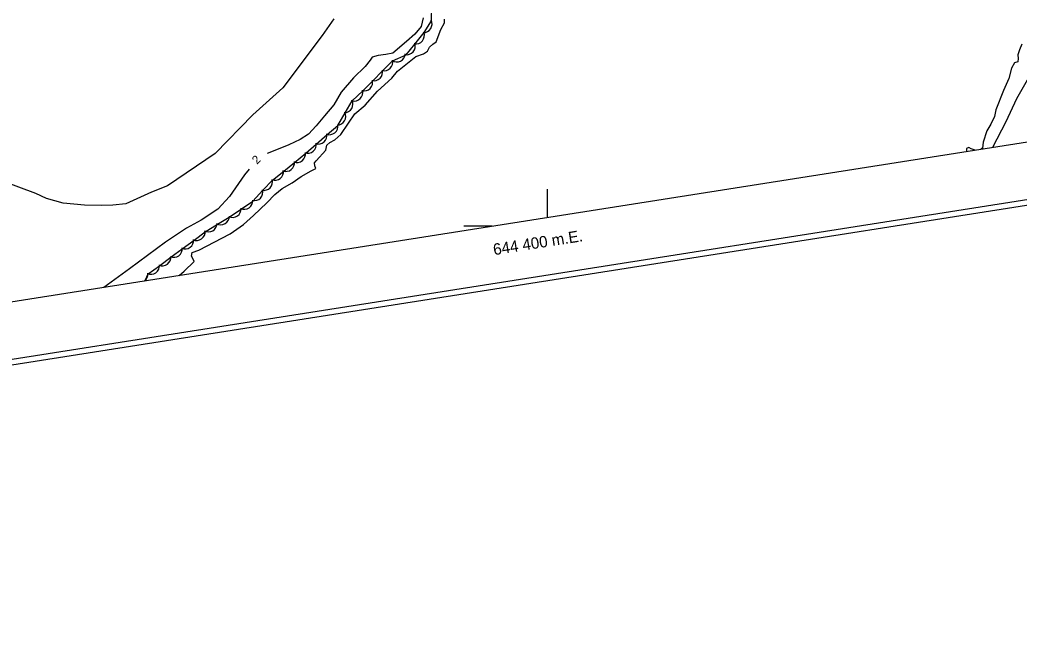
# Model space of a CAD drawing. Extents: x 643342 to 646936, y 5873857 to 5876103.
# Drawn here: x 644214.5 to 644566.3, y 5873857 to 5874072.5 of the extents above; entities that cross this region are included whole.
import ezdxf

# ---------------------------------------------------------------- set-up
doc = ezdxf.new("R2010")
doc.units = 0
for name, color, linetype in [('Niveau 2', 7, 'Continuous'), ('Niveau 22', 7, 'Continuous'), ('Niveau 4', 7, 'Continuous'), ('Niveau 44', 7, 'Continuous'), ('Niveau 60', 7, 'Continuous'), ('Niveau 61', 7, 'Continuous')]:
    doc.layers.add(name, color=color, linetype=linetype)

msp = doc.modelspace()

# ---------------------------------------------------------------- linework, layer by layer
at = {"layer": 'Niveau 2'}
for points in [[(644324.94, 5874072.94), (644320.84, 5874067.04), (644306.96, 5874048.61), (644296.44, 5874039.2), (644283.1, 5874025.54), (644266.37, 5874014.18), (644260.79, 5874011.93), (644251.7, 5874007.83), (644247.13, 5874007.43), (644243.24, 5874007.32), (644237.22, 5874007.38), (644229.71, 5874008.14), (644223.79, 5874009.74), (644220.09, 5874011.54), (644207.04, 5874016.28)], [(644356.35, 5874073.26), (644355.55, 5874070.24), (644353.41, 5874067.57), (644350.45, 5874064.95), (644345.59, 5874060.86), (644343.15, 5874060.41), (644340.46, 5874060.06), (644338.39, 5874059.41), (644337.65, 5874058.4), (644335.95, 5874056.12), (644331.8, 5874052.22), (644327.5, 5874047.12), (644324.93, 5874042.65), (644321.6, 5874038.81), (644318.71, 5874035.26), (644316, 5874032.42), (644313.09, 5874030.52), (644309, 5874028.62), (644304.66, 5874026.83), (644301.43, 5874025.58)], [(644295.13, 5874020.03), (644293.48, 5874018.06), (644288.23, 5874010.41), (644284.12, 5874006.03), (644278.19, 5874002.09), (644273, 5873999.28), (644265.62, 5873994.39), (644252.96, 5873985.02), (644243.96, 5873978.51)]]:
    msp.add_lwpolyline(points, dxfattribs=at)
at = {"layer": 'Niveau 22'}
msp.add_lwpolyline([(644570.62, 5874054.68), (644565.06, 5874044.75), (644561.24, 5874036.74), (644556.53, 5874027.68)], dxfattribs=at)
at = {"layer": 'Niveau 4'}
for points in [[(644270.49, 5873982.68), (644272.29, 5873984.23), (644275.78, 5873987.61), (644275.34, 5873988.63), (644274.79, 5873989.53), (644275.04, 5873990.73), (644277.45, 5873991.53), (644288.43, 5873997.34), (644293.12, 5874000.58), (644296.64, 5874003.73), (644301.33, 5874008.27), (644304.17, 5874011.12), (644306.71, 5874013.23), (644310.2, 5874015.31), (644313.44, 5874017.48), (644316.94, 5874019.44), (644318.52, 5874020.29), (644318.21, 5874021.21), (644318.12, 5874022.26), (644318.65, 5874023.02), (644322.11, 5874026.75), (644322.43, 5874028.55), (644323.42, 5874029.46), (644325.24, 5874030.33), (644327.32, 5874032.29), (644330.06, 5874036.19), (644332.25, 5874039.57), (644335.9, 5874042.61), (644340.22, 5874047.48), (644345.27, 5874052.06), (644347.31, 5874054.48), (644350.18, 5874056.86), (644353.73, 5874059.65), (644356.37, 5874060.59), (644357.83, 5874061.55), (644358.54, 5874062.91), (644359.75, 5874063.96), (644360.86, 5874064.89), (644362.5, 5874069.17), (644363.84, 5874071.53), (644363.85, 5874072.83)], [(644566.86, 5874063.97), (644566.08, 5874062.02), (644565.51, 5874060.31), (644565.62, 5874059.02), (644565.48, 5874057.83), (644564.33, 5874057.49), (644563.3, 5874055.63), (644562.31, 5874051.89), (644560.42, 5874047.71), (644557.79, 5874040.98), (644557.28, 5874038.58), (644555.97, 5874035.87), (644554.63, 5874033.51), (644553.31, 5874029.5), (644553.01, 5874027.47), (644552.52, 5874027.05)], [(644550.53, 5874026.74), (644549.13, 5874027.24), (644548.27, 5874027.64), (644547.47, 5874027.33), (644547.43, 5874026.25)]]:
    msp.add_lwpolyline(points, dxfattribs=at)
at = {"layer": 'Niveau 44'}
msp.add_lwpolyline([(644258.51, 5873980.96), (644259.6, 5873983.25), (644263.53, 5873986.1), (644267.65, 5873989.19), (644271.55, 5873992.09), (644275.7, 5873995.13), (644279.61, 5873998), (644283.91, 5874000.77), (644288.11, 5874003.19), (644292.37, 5874006.12), (644296.37, 5874008.87), (644299.94, 5874012.65), (644303.28, 5874016.17), (644307.26, 5874019.38), (644311.03, 5874022.44), (644315.01, 5874025.72), (644318.68, 5874028.89), (644322.59, 5874032.24), (644326.29, 5874035.37), (644328.92, 5874039.91), (644331.36, 5874044.1), (644335.1, 5874047.59), (644338.49, 5874051.06), (644342.12, 5874054.7), (644345.56, 5874058.13), (644350.3, 5874060.29), (644353.43, 5874064.01), (644356.61, 5874068.08), (644359.22, 5874072.17), (644359.37, 5874077.62)], dxfattribs=at)
for centre, start, end in [((644356.43, 5874071.08), 267.4361, 27.414), ((644356.43, 5874071.08), 267.4361, 27.414), ((644356.43, 5874071.08), 267.4361, 27.414), ((644353.74, 5874067.11), 259.9265, 19.9045), ((644353.74, 5874067.11), 259.9265, 19.9045), ((644353.74, 5874067.11), 259.9265, 19.9045), ((644350.52, 5874063.29), 259.9265, 19.9045), ((644350.52, 5874063.29), 259.9265, 19.9045), ((644350.52, 5874063.29), 259.9265, 19.9045), ((644342.6, 5874057.67), 254.8586, 14.8366), ((644342.6, 5874057.67), 254.8586, 14.8366), ((644342.6, 5874057.67), 254.8586, 14.8366), ((644347.03, 5874060.77), 236.7841, 356.762), ((644347.03, 5874060.77), 236.7841, 356.762), ((644347.03, 5874060.77), 236.7841, 356.762), ((644339.05, 5874054.14), 254.8586, 14.8366), ((644339.05, 5874054.14), 254.8586, 14.8366), ((644339.05, 5874054.14), 254.8586, 14.8366), ((644335.54, 5874050.56), 255.5933, 15.5712), ((644335.54, 5874050.56), 255.5933, 15.5712), ((644335.54, 5874050.56), 255.5933, 15.5712), ((644332.04, 5874046.99), 255.5933, 15.5712), ((644332.04, 5874046.99), 255.5933, 15.5712), ((644332.04, 5874046.99), 255.5933, 15.5712), ((644328.61, 5874042.89), 269.8006, 29.7786), ((644328.61, 5874042.89), 269.8006, 29.7786), ((644328.61, 5874042.89), 269.8006, 29.7786), ((644326.1, 5874038.57), 269.8006, 29.7786), ((644326.1, 5874038.57), 269.8006, 29.7786), ((644326.1, 5874038.57), 269.8006, 29.7786), ((644323.3, 5874035.15), 250.2203, 10.1982), ((644323.3, 5874035.15), 250.2203, 10.1982), ((644323.3, 5874035.15), 250.2203, 10.1982), ((644319.48, 5874031.9), 250.7842, 10.7622), ((644319.48, 5874031.9), 250.7842, 10.7622), ((644319.48, 5874031.9), 250.7842, 10.7622), ((644315.69, 5874028.64), 250.7842, 10.7622), ((644315.69, 5874028.64), 250.7842, 10.7622), ((644315.69, 5874028.64), 250.7842, 10.7622), ((644308.04, 5874022.28), 249.0518, 9.0298), ((644308.04, 5874022.28), 249.0518, 9.0298), ((644308.04, 5874022.28), 249.0518, 9.0298), ((644311.92, 5874025.43), 249.0518, 9.0298), ((644311.92, 5874025.43), 249.0518, 9.0298), ((644311.92, 5874025.43), 249.0518, 9.0298), ((644304.15, 5874019.13), 249.0518, 9.0298), ((644304.15, 5874019.13), 249.0518, 9.0298), ((644304.15, 5874019.13), 249.0518, 9.0298), ((644300.33, 5874015.62), 256.5684, 16.5464), ((644300.33, 5874015.62), 256.5684, 16.5464), ((644300.33, 5874015.62), 256.5684, 16.5464), ((644296.89, 5874011.99), 256.5684, 16.5464), ((644296.89, 5874011.99), 256.5684, 16.5464), ((644296.89, 5874011.99), 256.5684, 16.5464), ((644293.37, 5874008.95), 244.5388, 4.5168), ((644293.37, 5874008.95), 244.5388, 4.5168), ((644293.37, 5874008.95), 244.5388, 4.5168), ((644289.25, 5874006.11), 244.5388, 4.5168), ((644289.25, 5874006.11), 244.5388, 4.5168), ((644289.25, 5874006.11), 244.5388, 4.5168), ((644285.13, 5874003.51), 239.9355, 359.9134), ((644285.13, 5874003.51), 239.9355, 359.9134), ((644285.13, 5874003.51), 239.9355, 359.9134), ((644276.61, 5873997.99), 246.2208, 6.1988), ((644276.61, 5873997.99), 246.2208, 6.1988), ((644276.61, 5873997.99), 246.2208, 6.1988), ((644280.8, 5874001.01), 239.9355, 359.9134), ((644280.8, 5874001.01), 239.9355, 359.9134), ((644280.8, 5874001.01), 239.9355, 359.9134), ((644272.58, 5873995.03), 246.2208, 6.1988), ((644272.58, 5873995.03), 246.2208, 6.1988), ((644272.58, 5873995.03), 246.2208, 6.1988), ((644268.55, 5873992.05), 246.6316, 6.6096), ((644268.55, 5873992.05), 246.6316, 6.6096), ((644268.55, 5873992.05), 246.6316, 6.6096), ((644264.53, 5873989.07), 246.6316, 6.6096), ((644264.53, 5873989.07), 246.6316, 6.6096), ((644264.53, 5873989.07), 246.6316, 6.6096), ((644260.53, 5873986.1), 245.9215, 5.8995), ((644260.53, 5873986.1), 245.9215, 5.8995), ((644260.53, 5873986.1), 245.9215, 5.8995), ((644256.48, 5873983.17), 306.4414, 5.8995), ((644256.48, 5873983.17), 306.4414, 5.8995), ((644256.48, 5873983.17), 306.4414, 5.8995)]:
    msp.add_arc(centre, 3, start, end, dxfattribs=at)
at = {"layer": 'Niveau 60'}
for p, q in [((644400, 5874003.06), (644400, 5874013.06)), ((644380.57, 5874000), (644370.57, 5874000))]:
    msp.add_line(p, q, dxfattribs=at)
for points in [[(643342.09, 5875579.85), (646664.86, 5876102.57), (646935.9, 5874379.74), (643613.15, 5873856.99), (643342.1, 5875579.83)], [(643342.09, 5875579.85), (646664.86, 5876102.57), (646935.9, 5874379.74), (643613.15, 5873856.99), (643342.1, 5875579.83)], [(643342.09, 5875579.85), (646664.86, 5876102.57), (646935.9, 5874379.74), (643613.15, 5873856.99), (643342.1, 5875579.83)], [(643344.38, 5875578.18), (646663.19, 5876100.29), (646933.6, 5874381.38), (643614.81, 5873859.28), (643344.38, 5875578.18)], [(643344.38, 5875578.18), (646663.19, 5876100.29), (646933.6, 5874381.38), (643614.81, 5873859.28), (643344.38, 5875578.18)], [(643344.38, 5875578.18), (646663.19, 5876100.29), (646933.6, 5874381.38), (643614.81, 5873859.28), (643344.38, 5875578.18)]]:
    msp.add_lwpolyline(points, dxfattribs=at)
msp.add_lwpolyline([(643367.26, 5875561.52), (646133.22, 5875996.67), (646397.42, 5874317.29), (643631.46, 5873882.15)], close=True, dxfattribs=at)

# ---------------------------------------------------------------- texts
at = {"layer": 'Niveau 2'}
msp.add_text('2', height=3, rotation=44.7847, dxfattribs=at).set_placement((644297.87, 5874021.56))
at = {"layer": 'Niveau 61'}
msp.add_text('644 400 m.E. ', height=4, rotation=8.9404, dxfattribs=at).set_placement((644381.25, 5873989.81))

doc.saveas('drawing.dxf')
